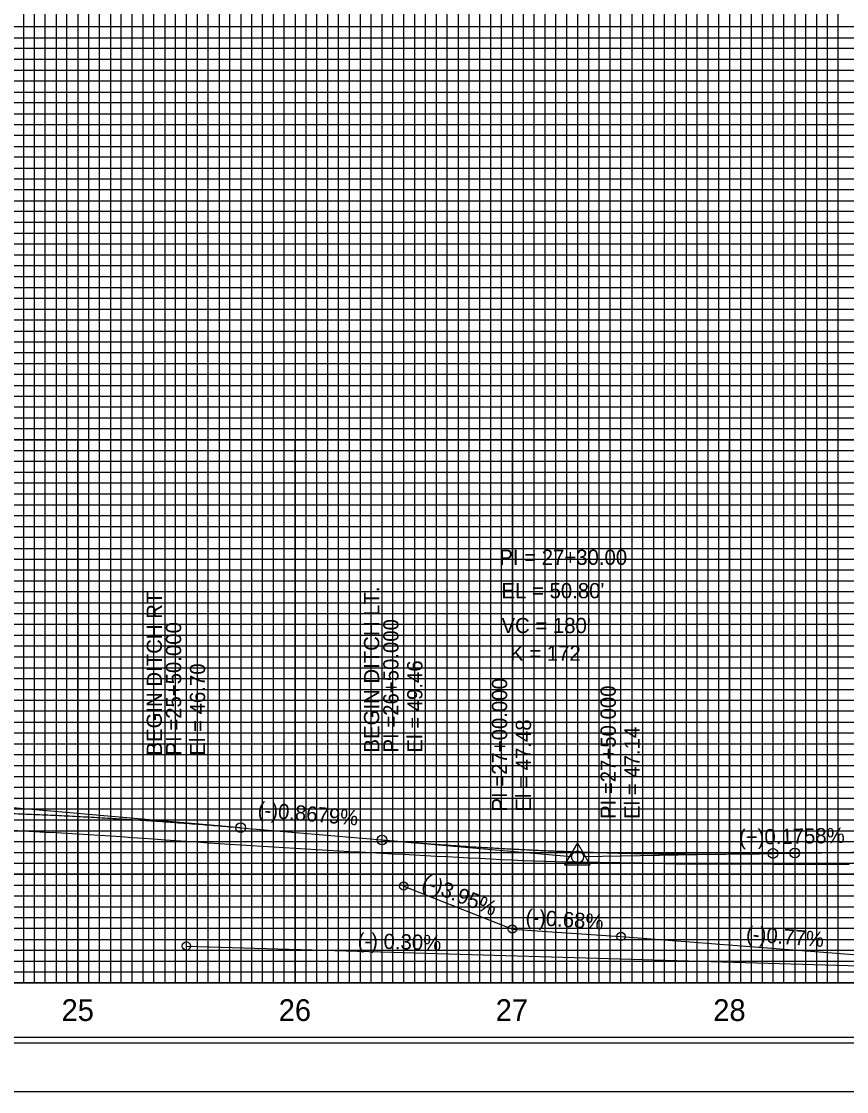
# Model space of a CAD drawing. Extents: x 2345490 to 2436403, y 465165 to 573888.
# Drawn here: x 2383154.5 to 2383534.3, y 536150.7 to 536643.2 of the extents above; entities that cross this region are included whole.
import ezdxf

# ---------------------------------------------------------------- set-up
doc = ezdxf.new("R2010")
doc.units = 0
for name, color, linetype in [('Old_Level_1', 7, 'Continuous'), ('Old_Level_18', 7, 'Continuous'), ('Old_Level_2', 7, 'Continuous'), ('Old_Level_3', 7, 'Continuous'), ('Old_Level_41', 7, 'Continuous'), ('Old_Level_42', 7, 'Continuous'), ('Old_Level_43', 7, 'Continuous'), ('Old_Level_50', 7, 'Continuous'), ('Old_Level_51', 7, 'Continuous'), ('Old_Level_57', 7, 'Continuous'), ('Old_Level_62', 7, 'Continuous')]:
    doc.layers.add(name, color=color, linetype=linetype)

msp = doc.modelspace()

# ---------------------------------------------------------------- linework, layer by layer
at = {"layer": 'Old_Level_1'}
for points in [[(2383150.454, 536270.972), (2383155.454, 536270.68925), (2383160.454, 536270.409), (2383165.454, 536270.1265), (2383170.454, 536269.844), (2383175.454, 536269.56125), (2383180.454, 536269.27875)], [(2383180.454, 536269.27875), (2383185.454, 536268.99625), (2383190.454, 536268.714), (2383195.454, 536268.36125), (2383200.454, 536268.0105), (2383205.454, 536267.66), (2383210.454, 536267.30925), (2383215.454, 536266.95875), (2383220.454, 536266.608), (2383225.454, 536266.2495), (2383230.454, 536265.8985), (2383235.454, 536265.54775), (2383240.454, 536265.20825), (2383245.454, 536264.89075), (2383250.454, 536264.563), (2383255.454, 536264.236), (2383260.454, 536263.91275), (2383265.454, 536263.5935), (2383270.454, 536263.28775), (2383275.454, 536262.98375), (2383280.454, 536262.67625), (2383285.454, 536262.3725), (2383290.454, 536262.0725), (2383295.454, 536261.811), (2383300.454, 536261.524), (2383305.454, 536261.24), (2383310.454, 536260.95925), (2383315.454, 536260.68125), (2383320.454, 536260.40625), (2383325.454, 536260.1445), (2383330.454, 536259.8735), (2383335.454, 536259.6055), (2383340.454, 536259.34), (2383345.454, 536259.06575), (2383350.454, 536258.80225), (2383355.454, 536258.545), (2383360.454, 536258.29375), (2383365.454, 536258.0485), (2383370.454, 536257.80925), (2383375.454, 536257.54425), (2383380.454, 536257.31775), (2383385.454, 536257.09875), (2383390.454, 536256.887), (2383395.454, 536256.6835), (2383400.454, 536256.57425), (2383405.454, 536256.47575), (2383410.454, 536256.38475), (2383415.454, 536256.3005), (2383420.454, 536256.218), (2383425.454, 536256.1355), (2383430.454, 536256.04775), (2383435.454, 536255.968), (2383440.454, 536255.8845), (2383445.454, 536255.76925), (2383450.454, 536255.654), (2383455.454, 536255.53875), (2383460.454, 536255.462), (2383465.454, 536255.45825), (2383470.454, 536255.4545), (2383475.454, 536255.45075), (2383480.454, 536255.447), (2383485.454, 536255.443), (2383490.454, 536255.426), (2383495.454, 536255.4215), (2383500.454, 536255.417), (2383505.454, 536255.4125), (2383510.454, 536255.408), (2383515.454, 536255.4035), (2383520.454, 536255.399), (2383525.454, 536255.376), (2383530.454, 536255.3565), (2383535.454, 536255.33725)]]:
    msp.add_lwpolyline(points, dxfattribs=at)
at = {"layer": 'Old_Level_18'}
msp.add_lwpolyline([(2384530.454, 537225.68175), (2383030.454, 537225.68175), (2383030.454, 536175.68175), (2384530.454, 536175.68175)], close=True, dxfattribs=at)
at = {"layer": 'Old_Level_2'}
for p, q in [((2383255.454, 536272.13349), (2383133.1937, 536282.74393)), ((2383255.454, 536272.13349), (2383320.454, 536266.49241)), ((2383320.454, 536266.49241), (2383407.7143, 536258.91947)), ((2383500.454, 536260.26352), (2383413.20358, 536258.73003)), ((2383500.454, 536260.26352), (2383510.454, 536260.43928)), ((2383510.454, 536260.43928), (2383572.70442, 536261.53337))]:
    msp.add_line(p, q, dxfattribs=at)
msp.add_lwpolyline([(2383404.52, 536255.0802), (2383416.2625, 536255.0802), (2383410.3915, 536265.20595)], close=True, dxfattribs=at)
for centre, radius in [((2383255.454, 536272.13349), 2.25), ((2383320.454, 536266.49241), 2.25), ((2383410.454, 536258.6817), 2.75), ((2383500.454, 536260.26352), 2.25), ((2383510.454, 536260.43928), 2.25)]:
    msp.add_circle(centre, radius, dxfattribs=at)
for points in [[(2383005.454, 536279.2317), (2383010.454, 536279.37586), (2383015.454, 536279.50834), (2383020.454, 536279.62915), (2383025.454, 536279.73827), (2383030.454, 536279.83572), (2383035.454, 536279.92149), (2383040.454, 536279.99557), (2383045.454, 536280.05799), (2383050.454, 536280.10872), (2383055.454, 536280.14777), (2383060.454, 536280.17515), (2383065.454, 536280.19084), (2383070.454, 536280.19486), (2383075.454, 536280.1872), (2383080.454, 536280.16786), (2383085.454, 536280.13684), (2383090.454, 536280.09415), (2383095.454, 536280.03977), (2383100.454, 536279.97372), (2383105.454, 536279.89599), (2383110.454, 536279.80658), (2383115.454, 536279.70549), (2383120.454, 536279.59272), (2383125.454, 536279.46827), (2383130.454, 536279.33215), (2383135.454, 536279.18434), (2383140.454, 536279.02486), (2383145.454, 536278.8537), (2383150.454, 536278.67086), (2383155.454, 536278.47634), (2383160.454, 536278.27015), (2383165.454, 536278.05227), (2383170.454, 536277.82272), (2383175.454, 536277.58149), (2383180.454, 536277.32858), (2383185.454, 536277.06399), (2383190.454, 536276.78772), (2383195.454, 536276.49977), (2383200.454, 536276.20015), (2383205.454, 536275.88884), (2383210.454, 536275.56586), (2383215.454, 536275.2312), (2383220.454, 536274.88486), (2383225.454, 536274.52684), (2383230.454, 536274.15715), (2383235.454, 536273.77577), (2383240.454, 536273.38272), (2383245.454, 536272.97799), (2383250.454, 536272.56157), (2383255.454, 536272.13349)], [(2383320.454, 536266.49241), (2383324.054, 536266.18374), (2383327.654, 536265.88259), (2383331.254, 536265.58894), (2383334.854, 536265.30281), (2383338.454, 536265.0242), (2383342.054, 536264.7531), (2383345.654, 536264.48951), (2383349.254, 536264.23343), (2383352.854, 536263.98488), (2383356.454, 536263.74383), (2383360.054, 536263.5103), (2383363.654, 536263.28428), (2383367.254, 536263.06578), (2383370.854, 536262.85479), (2383374.454, 536262.65131), (2383378.054, 536262.45535), (2383381.654, 536262.26691), (2383385.254, 536262.08597), (2383388.854, 536261.91255), (2383392.454, 536261.74665), (2383396.054, 536261.58826), (2383399.654, 536261.43738), (2383403.254, 536261.29402), (2383406.854, 536261.15817), (2383410.454, 536261.02983), (2383414.054, 536260.90901), (2383417.654, 536260.79571), (2383421.254, 536260.68991), (2383424.854, 536260.59163), (2383428.454, 536260.50087), (2383432.054, 536260.41762), (2383435.654, 536260.34188), (2383439.254, 536260.27366), (2383442.854, 536260.21295), (2383446.454, 536260.15976), (2383450.054, 536260.11407), (2383453.654, 536260.07591), (2383457.254, 536260.04526), (2383460.854, 536260.02212), (2383464.454, 536260.00649), (2383468.054, 536259.99838), (2383471.654, 536259.99779), (2383475.254, 536260.0047), (2383478.854, 536260.01913), (2383482.454, 536260.04108), (2383486.054, 536260.07054), (2383489.654, 536260.10751), (2383493.254, 536260.152), (2383496.854, 536260.204), (2383500.454, 536260.26352)], [(2383510.454, 536260.43928), (2383513.054, 536260.48373), (2383515.654, 536260.52569), (2383518.254, 536260.56516), (2383520.854, 536260.60214), (2383523.454, 536260.63663), (2383526.054, 536260.66862), (2383528.654, 536260.69813), (2383531.254, 536260.72515), (2383533.854, 536260.74967), (2383536.454, 536260.77171), (2383539.054, 536260.79125), (2383541.654, 536260.80831), (2383544.254, 536260.82287), (2383546.854, 536260.83494), (2383549.454, 536260.84453), (2383552.054, 536260.85162), (2383554.654, 536260.85622), (2383557.254, 536260.85833), (2383559.854, 536260.85794), (2383562.454, 536260.85507), (2383565.054, 536260.84971), (2383567.654, 536260.84186), (2383570.254, 536260.83151), (2383572.854, 536260.81868), (2383575.454, 536260.80335), (2383578.054, 536260.78554), (2383580.654, 536260.76523), (2383583.254, 536260.74243), (2383585.854, 536260.71714), (2383588.454, 536260.68936), (2383591.054, 536260.65909), (2383593.654, 536260.62633), (2383596.254, 536260.59108), (2383598.854, 536260.55334), (2383601.454, 536260.51311), (2383604.054, 536260.47038), (2383606.654, 536260.42517), (2383609.254, 536260.37747), (2383611.854, 536260.32727), (2383614.454, 536260.27458), (2383617.054, 536260.21941), (2383619.654, 536260.16174), (2383622.254, 536260.10158), (2383624.854, 536260.03893), (2383627.454, 536259.97379), (2383630.054, 536259.90616), (2383632.654, 536259.83604), (2383635.254, 536259.76343), (2383637.854, 536259.68833), (2383640.454, 536259.61073)]]:
    msp.add_spline(points, degree=3, dxfattribs=at)
at = {"layer": 'Old_Level_3'}
for p, q in [((2383230.45406, 536217.68175), (2383230.45406, 536387.26806)), ((2383330.45415, 536245.28175), (2383330.45415, 536380.78212)), ((2383380.45408, 536225.48175), (2383380.45408, 536346.95666)), ((2383380.45408, 536225.48175), (2383380.45408, 536344.24113)), ((2383430.45408, 536222.08175), (2383430.45408, 536343.55666)), ((2383430.45408, 536222.08175), (2383430.45408, 536340.84113)), ((2383330.45415, 536245.28175), (2383380.45408, 536225.48175)), ((2383380.45408, 536225.48175), (2383380.45408, 536225.48175)), ((2383380.45408, 536225.48175), (2383430.45408, 536222.08175)), ((2383430.45408, 536222.08175), (2383580.45389, 536210.48175)), ((2383230.45406, 536217.68175), (2383870.45371, 536198.68175))]:
    msp.add_line(p, q, dxfattribs=at)
for centre in [(2383330.45415, 536245.28175), (2383380.45408, 536225.48175), (2383230.45406, 536217.68175), (2383430.45408, 536222.08175)]:
    msp.add_circle(centre, 1.88794, dxfattribs=at)
at = {"layer": 'Old_Level_41'}
msp.add_line((2384530.454, 536200.68175), (2383030.454, 536200.68175), dxfattribs=at)
for points in [[(2383155.454, 537225.68175), (2383155.454, 536200.68175), (2383205.454, 536200.68175), (2383205.454, 537225.68175)], [(2383180.454, 537225.68175), (2383180.454, 536200.68175), (2383230.454, 536200.68175), (2383230.454, 537225.68175)], [(2383255.454, 537225.68175), (2383255.454, 536200.68175), (2383305.454, 536200.68175), (2383305.454, 537225.68175)], [(2383280.454, 537225.68175), (2383280.454, 536200.68175), (2383330.454, 536200.68175), (2383330.454, 537225.68175)], [(2383355.454, 537225.68175), (2383355.454, 536200.68175), (2383405.454, 536200.68175), (2383405.454, 537225.68175)], [(2383380.454, 537225.68175), (2383380.454, 536200.68175), (2383430.454, 536200.68175), (2383430.454, 537225.68175)], [(2383455.454, 537225.68175), (2383455.454, 536200.68175), (2383505.454, 536200.68175), (2383505.454, 537225.68175)], [(2383480.454, 537225.68175), (2383480.454, 536200.68175), (2383530.454, 536200.68175), (2383530.454, 537225.68175)], [(2384530.454, 536625.68175), (2383030.454, 536625.68175), (2383030.454, 536575.68175), (2384530.454, 536575.68175)], [(2384530.454, 536550.68175), (2383030.454, 536550.68175), (2383030.454, 536600.68175), (2384530.454, 536600.68175)], [(2384530.454, 536525.68175), (2383030.454, 536525.68175), (2383030.454, 536475.68175), (2384530.454, 536475.68175)], [(2384530.454, 536450.68175), (2383030.454, 536450.68175), (2383030.454, 536500.68175), (2384530.454, 536500.68175)], [(2384530.454, 536425.68175), (2383030.454, 536425.68175), (2383030.454, 536375.68175), (2384530.454, 536375.68175)], [(2384530.454, 536325.68175), (2383030.454, 536325.68175), (2383030.454, 536275.68175), (2384530.454, 536275.68175)], [(2384530.454, 536250.68175), (2383030.454, 536250.68175), (2383030.454, 536300.68175), (2384530.454, 536300.68175)], [(2384530.454, 536225.68175), (2383030.454, 536225.68175)]]:
    msp.add_lwpolyline(points, dxfattribs=at)
at = {"layer": 'Old_Level_42'}
msp.add_lwpolyline([(2384530.454, 536350.68175), (2383030.454, 536350.68175), (2383030.454, 536400.68175), (2384530.454, 536400.68175)], dxfattribs=at)
at = {"layer": 'Old_Level_43'}
for points in [[(2383160.454, 537225.68175), (2383160.454, 536200.68175), (2383165.454, 536200.68175), (2383165.454, 537225.68175)], [(2383170.454, 537225.68175), (2383170.454, 536200.68175), (2383175.454, 536200.68175), (2383175.454, 537225.68175)], [(2383185.454, 537225.68175), (2383185.454, 536200.68175), (2383190.454, 536200.68175), (2383190.454, 537225.68175)], [(2383195.454, 537225.68175), (2383195.454, 536200.68175), (2383200.454, 536200.68175), (2383200.454, 537225.68175)], [(2383210.454, 537225.68175), (2383210.454, 536200.68175), (2383215.454, 536200.68175), (2383215.454, 537225.68175)], [(2383220.454, 537225.68175), (2383220.454, 536200.68175), (2383225.454, 536200.68175), (2383225.454, 537225.68175)], [(2383235.454, 537225.68175), (2383235.454, 536200.68175), (2383240.454, 536200.68175), (2383240.454, 537225.68175)], [(2383245.454, 536200.68175), (2383250.454, 536200.68175), (2383250.454, 537225.68175)], [(2383245.454, 537225.68175), (2383245.454, 536200.68175)], [(2383260.454, 537225.68175), (2383260.454, 536200.68175), (2383265.454, 536200.68175), (2383265.454, 537225.68175)], [(2383270.454, 537225.68175), (2383270.454, 536200.68175), (2383275.454, 536200.68175), (2383275.454, 537225.68175)], [(2383285.454, 537225.68175), (2383285.454, 536200.68175), (2383290.454, 536200.68175), (2383290.454, 537225.68175)], [(2383295.454, 537225.68175), (2383295.454, 536200.68175), (2383300.454, 536200.68175), (2383300.454, 537225.68175)], [(2383310.454, 537225.68175), (2383310.454, 536200.68175), (2383315.454, 536200.68175), (2383315.454, 537225.68175)], [(2383320.454, 537225.68175), (2383320.454, 536200.68175), (2383325.454, 536200.68175), (2383325.454, 537225.68175)], [(2383335.454, 537225.68175), (2383335.454, 536200.68175), (2383340.454, 536200.68175), (2383340.454, 537225.68175)], [(2383345.454, 537225.68175), (2383345.454, 536200.68175), (2383350.454, 536200.68175), (2383350.454, 537225.68175)], [(2383360.454, 537225.68175), (2383360.454, 536200.68175), (2383365.454, 536200.68175), (2383365.454, 537225.68175)], [(2383370.454, 537225.68175), (2383370.454, 536200.68175), (2383375.454, 536200.68175), (2383375.454, 537225.68175)], [(2383385.454, 537225.68175), (2383385.454, 536200.68175), (2383390.454, 536200.68175), (2383390.454, 537225.68175)], [(2383395.454, 537225.68175), (2383395.454, 536200.68175), (2383400.454, 536200.68175), (2383400.454, 537225.68175)], [(2383410.454, 537225.68175), (2383410.454, 536200.68175), (2383425.454, 536200.68175), (2383425.454, 537225.68175)], [(2383415.454, 537225.68175), (2383415.454, 536200.68175), (2383420.454, 536200.68175), (2383420.454, 537225.68175)], [(2383415.454, 537225.08175), (2383415.454, 536200.68175), (2383420.454, 536200.68175), (2383420.454, 537225.08175)], [(2383435.454, 537225.68175), (2383435.454, 536200.68175), (2383440.454, 536200.68175), (2383440.454, 537225.68175)], [(2383445.454, 537225.68175), (2383445.454, 536200.68175), (2383450.454, 536200.68175), (2383450.454, 537225.68175)], [(2383460.454, 537225.68175), (2383460.454, 536200.68175), (2383465.454, 536200.68175), (2383465.454, 537225.68175)], [(2383470.454, 537225.68175), (2383470.454, 536200.68175), (2383475.454, 536200.68175), (2383475.454, 537225.68175)], [(2383485.454, 537225.68175), (2383485.454, 536200.68175), (2383490.454, 536200.68175), (2383490.454, 537225.68175)], [(2383495.454, 537225.68175), (2383495.454, 536200.68175), (2383500.454, 536200.68175), (2383500.454, 537225.68175)], [(2383510.454, 537225.68175), (2383510.454, 536200.68175), (2383515.454, 536200.68175), (2383515.454, 537225.68175)], [(2383520.454, 537225.68175), (2383520.454, 536200.68175), (2383525.454, 536200.68175), (2383525.454, 537225.68175)], [(2384480.454, 536640.68175), (2383080.454, 536640.68175), (2383080.454, 536635.68175), (2384480.454, 536635.68175)], [(2384480.454, 536630.68175), (2383080.454, 536630.68175), (2383080.454, 536620.68175), (2384480.454, 536620.68175)], [(2384480.454, 536615.68175), (2383080.454, 536615.68175), (2383080.454, 536610.68175), (2384480.454, 536610.68175)], [(2384480.454, 536605.68175), (2383080.454, 536605.68175), (2383080.454, 536595.68175), (2384480.454, 536595.68175)], [(2384480.454, 536590.68175), (2383080.454, 536590.68175), (2383080.454, 536585.68175), (2384480.454, 536585.68175)], [(2384480.454, 536580.68175), (2383080.454, 536580.68175), (2383080.454, 536570.68175), (2384480.454, 536570.68175)], [(2384480.454, 536565.68175), (2383080.454, 536565.68175), (2383080.454, 536560.68175), (2384480.454, 536560.68175)], [(2384480.454, 536555.68175), (2383080.454, 536555.68175), (2383080.454, 536545.68175), (2384480.454, 536545.68175)], [(2384480.454, 536540.68175), (2383080.454, 536540.68175), (2383080.454, 536535.68175), (2384480.454, 536535.68175)], [(2384480.454, 536530.68175), (2383080.454, 536530.68175), (2383080.454, 536520.68175), (2384480.454, 536520.68175)], [(2384480.454, 536515.68175), (2383080.454, 536515.68175), (2383080.454, 536510.68175), (2384480.454, 536510.68175)], [(2384480.454, 536505.68175), (2383080.454, 536505.68175), (2383080.454, 536495.68175), (2384480.454, 536495.68175)], [(2384480.454, 536490.68175), (2383080.454, 536490.68175), (2383080.454, 536485.68175), (2384480.454, 536485.68175)], [(2384480.454, 536480.68175), (2383080.454, 536480.68175), (2383080.454, 536470.68175), (2384480.454, 536470.68175)], [(2384480.454, 536465.68175), (2383080.454, 536465.68175), (2383080.454, 536460.68175), (2384480.454, 536460.68175)], [(2384480.454, 536455.68175), (2383080.454, 536455.68175), (2383080.454, 536445.68175), (2384480.454, 536445.68175)], [(2384480.454, 536440.68175), (2383080.454, 536440.68175), (2383080.454, 536435.68175), (2384480.454, 536435.68175)], [(2384480.454, 536430.68175), (2383080.454, 536430.68175), (2383080.454, 536420.68175), (2384480.454, 536420.68175)], [(2384480.454, 536415.68175), (2383080.454, 536415.68175), (2383080.454, 536410.68175), (2384480.454, 536410.68175)], [(2384480.454, 536405.68175), (2383080.454, 536405.68175)], [(2383080.454, 536395.68175), (2384480.454, 536395.68175)], [(2384480.454, 536390.68175), (2383080.454, 536390.68175), (2383080.454, 536385.68175), (2384480.454, 536385.68175)], [(2384480.454, 536380.68175), (2383080.454, 536380.68175)], [(2383080.454, 536370.68175), (2384480.454, 536370.68175)], [(2384480.454, 536365.68175), (2383080.454, 536365.68175), (2383080.454, 536360.68175), (2384480.454, 536360.68175)], [(2384480.454, 536355.68175), (2383080.454, 536355.68175), (2383080.454, 536345.68175), (2384480.454, 536345.68175)], [(2384480.454, 536340.68175), (2383080.454, 536340.68175), (2383080.454, 536335.68175), (2384480.454, 536335.68175)], [(2384480.454, 536330.68175), (2383080.454, 536330.68175), (2383080.454, 536320.68175), (2384480.454, 536320.68175)], [(2384480.454, 536315.68175), (2383080.454, 536315.68175), (2383080.454, 536310.68175), (2384480.454, 536310.68175)], [(2384480.454, 536305.68175), (2383080.454, 536305.68175), (2383080.454, 536295.68175), (2384480.454, 536295.68175)], [(2384480.454, 536290.68175), (2383080.454, 536290.68175), (2383080.454, 536285.68175), (2384480.454, 536285.68175)], [(2384480.454, 536280.68175), (2383080.454, 536280.68175), (2383080.454, 536270.68175), (2384480.454, 536270.68175)], [(2384480.454, 536265.68175), (2383080.454, 536265.68175), (2383080.454, 536260.68175), (2384480.454, 536260.68175)], [(2384480.454, 536255.68175), (2383080.454, 536255.68175), (2383080.454, 536245.68175), (2384480.454, 536245.68175)], [(2384480.454, 536240.68175), (2383080.454, 536240.68175), (2383080.454, 536235.68175), (2384480.454, 536235.68175)], [(2384480.454, 536230.68175), (2383080.454, 536230.68175), (2383080.454, 536220.68175), (2384480.454, 536220.68175)], [(2384480.454, 536215.68175), (2383080.454, 536215.68175), (2383080.454, 536210.68175), (2384480.454, 536210.68175)], [(2384480.454, 536205.68175), (2383080.454, 536205.68175)]]:
    msp.add_lwpolyline(points, dxfattribs=at)
at = {"layer": 'Old_Level_50'}
msp.add_lwpolyline([(2384542.954, 537228.23175), (2382876.454, 537228.23175), (2382876.454, 536173.13175), (2384542.954, 536173.13175)], close=True, dxfattribs=at)
at = {"layer": 'Old_Level_51'}
msp.add_lwpolyline([(2384547.454, 537250.68175), (2382863.454, 537250.68175), (2382863.454, 536150.68175), (2384547.454, 536150.68175)], close=True, dxfattribs=at)
at = {"layer": 'Old_Level_57'}
for p, q in [((2381630.45425, 536450.682), (2383880.45375, 536450.682)), ((2383180.45375, 536200.682), (2383180.45375, 536450.682)), ((2383180.45375, 536200.782), (2383180.45375, 536450.682)), ((2383280.45375, 536200.682), (2383280.45375, 536450.682)), ((2383280.45375, 536200.782), (2383280.45375, 536450.682)), ((2383380.45375, 536200.682), (2383380.45375, 536450.682)), ((2383380.45375, 536200.782), (2383380.45375, 536450.682)), ((2383480.45375, 536200.682), (2383480.45375, 536450.682)), ((2383480.45375, 536200.782), (2383480.45375, 536450.682)), ((2383480.45375, 536200.782), (2383480.45375, 536450.682)), ((2381630.45425, 536400.682), (2383880.45375, 536400.682)), ((2381630.45425, 536350.682), (2383880.45375, 536350.682)), ((2381630.45425, 536300.682), (2383880.45375, 536300.682)), ((2381630.454, 536250.682), (2383880.45375, 536250.682)), ((2381630.45425, 536200.682), (2383880.45375, 536200.682))]:
    msp.add_line(p, q, dxfattribs=at)

# ---------------------------------------------------------------- texts
at = {"layer": 'Old_Level_2'}
for s, height, p in [('PI = 27+30.00', 7.0000005, (2383374.46287, 536393.09188)), ("EL = 50.80'", 7.0000005, (2383375.454, 536377.71717)), ("VC = 180'", 7.000001, (2383375.454, 536361.6817)), ('K = 172', 7.000001, (2383379.41853, 536348.92111))]:
    msp.add_text(s, height=height, dxfattribs=at).set_placement(p)
for s, rotation, p in [('(-)0.8679%', 355.0399725, (2383263.06757, 536277.09968)), ('(+)0.1758%', 1.0069131, (2383484.81613, 536264.26204))]:
    msp.add_text(s, height=7, rotation=rotation, dxfattribs=at).set_placement(p)
at = {"layer": 'Old_Level_3'}
for s, height, rotation, p in [('BEGIN DITCH LT.', 7.0000005, 90, (2383319.17525, 536306.7119)), ('BEGIN DITCH RT', 7.0000005, 90, (2383219.17516, 536305.31799)), ('PI =26+50.000', 7.0000005, 90, (2383328.04915, 536306.7119)), ('PI =25+50.000', 7.0000005, 90, (2383228.04906, 536305.31799)), ('El = 46.70', 7.000001, 90, (2383239.04906, 536305.31799)), ('El = 49.46', 7.000001, 90, (2383339.04915, 536306.7119)), ('PI =27+00.000', 7.0000005, 90, (2383378.04908, 536279.54159)), ('PI =27+50.000', 7.0000005, 90, (2383428.04908, 536276.14159)), ('El = 47.48', 7.000001, 90, (2383389.04908, 536279.54159)), ('El = 47.14', 7.000001, 90, (2383439.04908, 536276.14159)), ('(-)3.95%', 7.000001, 338.3964046, (2383338.23842, 536244.53798)), ('(-)0.68%', 7.000001, 356.1098756, (2383386.36201, 536227.66915)), ('(-)0.77%', 7.000001, 355.5779223, (2383487.81537, 536219.95037)), ('(-) 0.30%', 7.000001, 358.2995301, (2383309.16205, 536216.74478))]:
    msp.add_text(s, height=height, rotation=rotation, dxfattribs=at).set_placement(p)
at = {"layer": 'Old_Level_62'}
for s, p in [('25', (2383172.998, 536183.18175)), ('26', (2383272.939, 536183.18175)), ('27', (2383372.7965, 536183.18175)), ('28', (2383472.92225, 536183.18175))]:
    msp.add_text(s, height=10.000001, dxfattribs=at).set_placement(p)

doc.saveas('drawing.dxf')
